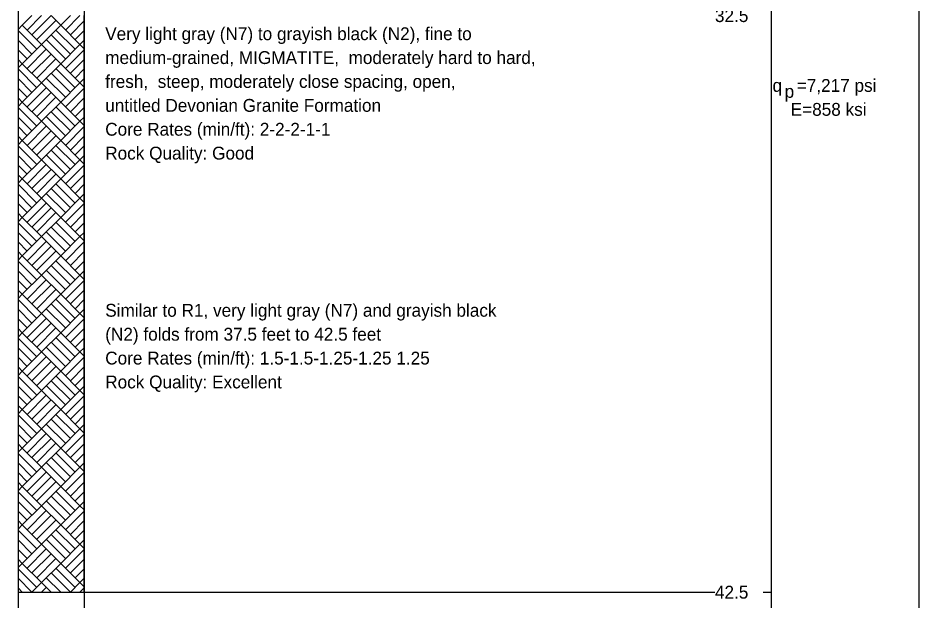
# Model space of a CAD drawing. Extents: x 9419 to 9552, y 6780 to 6865.
# Drawn here: x 9514.02 to 9529.65, y 6804.32 to 6814.43 of the extents above; entities that cross this region are included whole.
import ezdxf

# ---------------------------------------------------------------- set-up
doc = ezdxf.new("R2010")
doc.units = 0
doc.layers.add('7', color=7, linetype='Continuous')
doc.layers.add('8', color=7, linetype='Continuous')

msp = doc.modelspace()

# ---------------------------------------------------------------- linework, layer by layer
at = {"layer": '7'}
for p, q in [((9514.023, 6814.468), (9514.023, 6804.468)), ((9515.171, 6804.468), (9515.171, 6814.468)), ((9514.023, 6804.468), (9515.171, 6804.468))]:
    msp.add_line(p, q, dxfattribs=at)
for points in [[(9514.023, 6821.996), (9514.023, 6796.941)], [(9515.171, 6821.996), (9515.171, 6796.941)], [(9527.089, 6821.996), (9527.089, 6796.941)], [(9529.654, 6821.996), (9529.654, 6791.95)], [(9515.171, 6804.468), (9526.114, 6804.468)], [(9526.953, 6804.468), (9527.089, 6804.468)]]:
    msp.add_lwpolyline(points, dxfattribs=at)
at = {"layer": '8'}
for p, q in [((9514.264, 6814.468), (9514.097, 6814.302)), ((9514.431, 6814.468), (9514.181, 6814.218)), ((9514.597, 6814.468), (9514.264, 6814.135)), ((9514.597, 6814.468), (9514.764, 6814.302)), ((9514.931, 6814.468), (9514.764, 6814.302)), ((9515.097, 6814.468), (9514.847, 6814.218)), ((9514.097, 6814.302), (9514.023, 6814.228)), ((9514.097, 6814.302), (9514.431, 6813.968)), ((9514.681, 6814.385), (9514.347, 6814.052)), ((9514.764, 6814.302), (9514.431, 6813.968)), ((9514.764, 6814.302), (9514.431, 6813.968)), ((9514.764, 6814.302), (9515.097, 6813.968)), ((9515.171, 6814.376), (9514.931, 6814.135)), ((9514.023, 6814.209), (9514.347, 6813.885)), ((9514.597, 6814.135), (9514.931, 6813.802)), ((9514.681, 6814.218), (9515.014, 6813.885)), ((9515.171, 6814.209), (9515.014, 6814.052)), ((9514.023, 6814.043), (9514.264, 6813.802)), ((9514.431, 6813.968), (9514.097, 6813.635)), ((9514.431, 6813.968), (9514.097, 6813.635)), ((9514.764, 6813.635), (9514.431, 6813.968)), ((9514.431, 6813.968), (9514.764, 6813.635)), ((9514.514, 6814.052), (9514.847, 6813.718)), ((9515.097, 6813.968), (9514.764, 6813.635)), ((9515.097, 6813.968), (9514.764, 6813.635)), ((9515.171, 6814.043), (9515.097, 6813.968)), ((9515.171, 6814.043), (9515.097, 6813.968)), ((9515.171, 6813.894), (9515.097, 6813.968)), ((9515.097, 6813.968), (9515.171, 6813.894)), ((9514.023, 6813.876), (9514.181, 6813.718)), ((9514.514, 6813.885), (9514.181, 6813.552)), ((9514.597, 6813.802), (9514.264, 6813.468)), ((9515.171, 6813.876), (9514.847, 6813.552)), ((9514.097, 6813.635), (9514.023, 6813.709)), ((9514.097, 6813.635), (9514.023, 6813.561)), ((9514.097, 6813.635), (9514.431, 6813.302)), ((9514.681, 6813.718), (9514.347, 6813.385)), ((9514.764, 6813.635), (9514.431, 6813.302)), ((9514.764, 6813.635), (9514.431, 6813.302)), ((9514.764, 6813.635), (9515.097, 6813.302)), ((9515.171, 6813.709), (9514.931, 6813.468)), ((9514.023, 6813.543), (9514.347, 6813.218)), ((9514.597, 6813.468), (9514.931, 6813.135)), ((9514.681, 6813.552), (9515.014, 6813.218)), ((9515.171, 6813.543), (9515.014, 6813.385)), ((9514.023, 6813.376), (9514.264, 6813.135)), ((9514.431, 6813.302), (9514.097, 6812.968)), ((9514.431, 6813.302), (9514.097, 6812.968)), ((9514.764, 6812.968), (9514.431, 6813.302)), ((9514.431, 6813.302), (9514.764, 6812.968)), ((9514.514, 6813.385), (9514.847, 6813.052)), ((9515.097, 6813.302), (9514.764, 6812.968)), ((9515.097, 6813.302), (9514.764, 6812.968)), ((9515.171, 6813.376), (9515.097, 6813.302)), ((9515.171, 6813.376), (9515.097, 6813.302)), ((9515.171, 6813.228), (9515.097, 6813.302)), ((9515.097, 6813.302), (9515.171, 6813.228)), ((9514.023, 6813.209), (9514.181, 6813.052)), ((9514.514, 6813.218), (9514.181, 6812.885)), ((9515.171, 6813.209), (9514.847, 6812.885)), ((9514.097, 6812.968), (9514.023, 6813.043)), ((9514.597, 6813.135), (9514.264, 6812.802)), ((9514.681, 6813.052), (9514.347, 6812.718)), ((9515.171, 6813.043), (9514.931, 6812.802)), ((9514.097, 6812.968), (9514.023, 6812.894)), ((9514.023, 6812.876), (9514.347, 6812.552)), ((9514.097, 6812.968), (9514.431, 6812.635)), ((9514.764, 6812.968), (9514.431, 6812.635)), ((9514.764, 6812.968), (9514.431, 6812.635)), ((9514.681, 6812.885), (9515.014, 6812.552)), ((9514.764, 6812.968), (9515.097, 6812.635)), ((9515.171, 6812.876), (9515.014, 6812.718)), ((9514.023, 6812.709), (9514.264, 6812.468)), ((9514.514, 6812.718), (9514.847, 6812.385)), ((9514.597, 6812.802), (9514.931, 6812.468)), ((9515.171, 6812.709), (9515.097, 6812.635)), ((9515.171, 6812.709), (9515.097, 6812.635)), ((9514.023, 6812.543), (9514.181, 6812.385)), ((9514.431, 6812.635), (9514.097, 6812.302)), ((9514.431, 6812.635), (9514.097, 6812.302)), ((9514.514, 6812.552), (9514.181, 6812.218)), ((9514.764, 6812.302), (9514.431, 6812.635)), ((9514.431, 6812.635), (9514.764, 6812.302)), ((9515.097, 6812.635), (9514.764, 6812.302)), ((9515.097, 6812.635), (9514.764, 6812.302)), ((9515.171, 6812.543), (9514.847, 6812.218)), ((9515.171, 6812.561), (9515.097, 6812.635)), ((9515.097, 6812.635), (9515.171, 6812.561)), ((9514.097, 6812.302), (9514.023, 6812.376)), ((9514.597, 6812.468), (9514.264, 6812.135)), ((9514.681, 6812.385), (9514.347, 6812.052)), ((9515.171, 6812.376), (9514.931, 6812.135)), ((9514.097, 6812.302), (9514.023, 6812.228)), ((9514.023, 6812.209), (9514.347, 6811.885)), ((9514.097, 6812.302), (9514.431, 6811.968)), ((9514.764, 6812.302), (9514.431, 6811.968)), ((9514.764, 6812.302), (9514.431, 6811.968)), ((9514.681, 6812.218), (9515.014, 6811.885)), ((9514.764, 6812.302), (9515.097, 6811.968)), ((9515.171, 6812.209), (9515.014, 6812.052)), ((9514.514, 6812.052), (9514.847, 6811.718)), ((9514.597, 6812.135), (9514.931, 6811.802)), ((9514.023, 6812.043), (9514.264, 6811.802)), ((9514.431, 6811.968), (9514.097, 6811.635)), ((9514.431, 6811.968), (9514.097, 6811.635)), ((9514.764, 6811.635), (9514.431, 6811.968)), ((9514.431, 6811.968), (9514.764, 6811.635)), ((9515.097, 6811.968), (9514.764, 6811.635)), ((9515.097, 6811.968), (9514.764, 6811.635)), ((9515.171, 6812.043), (9515.097, 6811.968)), ((9515.171, 6812.043), (9515.097, 6811.968)), ((9515.171, 6811.894), (9515.097, 6811.968)), ((9515.097, 6811.968), (9515.171, 6811.894)), ((9514.023, 6811.876), (9514.181, 6811.718)), ((9514.514, 6811.885), (9514.181, 6811.552)), ((9514.597, 6811.802), (9514.264, 6811.468)), ((9515.171, 6811.876), (9514.847, 6811.552)), ((9514.097, 6811.635), (9514.023, 6811.709)), ((9514.097, 6811.635), (9514.023, 6811.561)), ((9514.097, 6811.635), (9514.431, 6811.302)), ((9514.681, 6811.718), (9514.347, 6811.385)), ((9514.764, 6811.635), (9514.431, 6811.302)), ((9514.764, 6811.635), (9514.431, 6811.302)), ((9514.764, 6811.635), (9515.097, 6811.302)), ((9515.171, 6811.709), (9514.931, 6811.468)), ((9514.023, 6811.543), (9514.347, 6811.218)), ((9514.597, 6811.468), (9514.931, 6811.135)), ((9514.681, 6811.552), (9515.014, 6811.218)), ((9515.171, 6811.543), (9515.014, 6811.385)), ((9514.023, 6811.376), (9514.264, 6811.135)), ((9514.431, 6811.302), (9514.097, 6810.968)), ((9514.431, 6811.302), (9514.097, 6810.968)), ((9514.764, 6810.968), (9514.431, 6811.302)), ((9514.431, 6811.302), (9514.764, 6810.968)), ((9514.514, 6811.385), (9514.847, 6811.052)), ((9515.097, 6811.302), (9514.764, 6810.968)), ((9515.097, 6811.302), (9514.764, 6810.968)), ((9515.171, 6811.376), (9515.097, 6811.302)), ((9515.171, 6811.376), (9515.097, 6811.302)), ((9515.171, 6811.228), (9515.097, 6811.302)), ((9515.097, 6811.302), (9515.171, 6811.228)), ((9514.023, 6811.209), (9514.181, 6811.052)), ((9514.514, 6811.218), (9514.181, 6810.885)), ((9514.597, 6811.135), (9514.264, 6810.802)), ((9515.171, 6811.209), (9514.847, 6810.885)), ((9514.097, 6810.968), (9514.023, 6811.043)), ((9514.097, 6810.968), (9514.023, 6810.894)), ((9514.097, 6810.968), (9514.431, 6810.635)), ((9514.681, 6811.052), (9514.347, 6810.718)), ((9514.764, 6810.968), (9514.431, 6810.635)), ((9514.764, 6810.968), (9514.431, 6810.635)), ((9514.764, 6810.968), (9515.097, 6810.635)), ((9515.171, 6811.043), (9514.931, 6810.802)), ((9514.023, 6810.876), (9514.347, 6810.552)), ((9514.597, 6810.802), (9514.931, 6810.468)), ((9514.681, 6810.885), (9515.014, 6810.552)), ((9515.171, 6810.876), (9515.014, 6810.718)), ((9514.023, 6810.709), (9514.264, 6810.468)), ((9514.514, 6810.718), (9514.847, 6810.385)), ((9515.171, 6810.709), (9515.097, 6810.635)), ((9515.171, 6810.709), (9515.097, 6810.635)), ((9514.023, 6810.543), (9514.181, 6810.385)), ((9514.431, 6810.635), (9514.097, 6810.302)), ((9514.431, 6810.635), (9514.097, 6810.302)), ((9514.514, 6810.552), (9514.181, 6810.218)), ((9514.764, 6810.302), (9514.431, 6810.635)), ((9514.431, 6810.635), (9514.764, 6810.302)), ((9515.097, 6810.635), (9514.764, 6810.302)), ((9515.097, 6810.635), (9514.764, 6810.302)), ((9515.171, 6810.543), (9514.847, 6810.218)), ((9515.171, 6810.561), (9515.097, 6810.635)), ((9515.097, 6810.635), (9515.171, 6810.561)), ((9514.097, 6810.302), (9514.023, 6810.376)), ((9514.597, 6810.468), (9514.264, 6810.135)), ((9514.681, 6810.385), (9514.347, 6810.052)), ((9515.171, 6810.376), (9514.931, 6810.135)), ((9514.097, 6810.302), (9514.023, 6810.228)), ((9514.023, 6810.209), (9514.347, 6809.885)), ((9514.097, 6810.302), (9514.431, 6809.968)), ((9514.764, 6810.302), (9514.431, 6809.968)), ((9514.764, 6810.302), (9514.431, 6809.968)), ((9514.681, 6810.218), (9515.014, 6809.885)), ((9514.764, 6810.302), (9515.097, 6809.968)), ((9515.171, 6810.209), (9515.014, 6810.052)), ((9514.023, 6810.043), (9514.264, 6809.802)), ((9514.514, 6810.052), (9514.847, 6809.718)), ((9514.597, 6810.135), (9514.931, 6809.802)), ((9515.171, 6810.043), (9515.097, 6809.968)), ((9515.171, 6810.043), (9515.097, 6809.968)), ((9514.023, 6809.876), (9514.181, 6809.718)), ((9514.431, 6809.968), (9514.097, 6809.635)), ((9514.431, 6809.968), (9514.097, 6809.635)), ((9514.514, 6809.885), (9514.181, 6809.552)), ((9514.764, 6809.635), (9514.431, 6809.968)), ((9514.431, 6809.968), (9514.764, 6809.635)), ((9515.097, 6809.968), (9514.764, 6809.635)), ((9515.097, 6809.968), (9514.764, 6809.635)), ((9515.171, 6809.876), (9514.847, 6809.552)), ((9515.171, 6809.894), (9515.097, 6809.968)), ((9515.097, 6809.968), (9515.171, 6809.894)), ((9514.097, 6809.635), (9514.023, 6809.709)), ((9514.597, 6809.802), (9514.264, 6809.468)), ((9514.681, 6809.718), (9514.347, 6809.385)), ((9515.171, 6809.709), (9514.931, 6809.468)), ((9514.097, 6809.635), (9514.023, 6809.561)), ((9514.097, 6809.635), (9514.431, 6809.302)), ((9514.764, 6809.635), (9514.431, 6809.302)), ((9514.764, 6809.635), (9514.431, 6809.302)), ((9514.681, 6809.552), (9515.014, 6809.218)), ((9514.764, 6809.635), (9515.097, 6809.302)), ((9514.023, 6809.543), (9514.347, 6809.218)), ((9514.597, 6809.468), (9514.931, 6809.135)), ((9515.171, 6809.543), (9515.014, 6809.385)), ((9514.023, 6809.376), (9514.264, 6809.135)), ((9514.431, 6809.302), (9514.097, 6808.968)), ((9514.431, 6809.302), (9514.097, 6808.968)), ((9514.764, 6808.968), (9514.431, 6809.302)), ((9514.431, 6809.302), (9514.764, 6808.968)), ((9514.514, 6809.385), (9514.847, 6809.052)), ((9515.097, 6809.302), (9514.764, 6808.968)), ((9515.097, 6809.302), (9514.764, 6808.968)), ((9515.171, 6809.376), (9515.097, 6809.302)), ((9515.171, 6809.376), (9515.097, 6809.302)), ((9515.171, 6809.228), (9515.097, 6809.302)), ((9515.097, 6809.302), (9515.171, 6809.228)), ((9514.023, 6809.209), (9514.181, 6809.052)), ((9514.514, 6809.218), (9514.181, 6808.885)), ((9514.597, 6809.135), (9514.264, 6808.802)), ((9515.171, 6809.209), (9514.847, 6808.885)), ((9514.097, 6808.968), (9514.023, 6809.043)), ((9514.097, 6808.968), (9514.023, 6808.894)), ((9514.097, 6808.968), (9514.431, 6808.635)), ((9514.681, 6809.052), (9514.347, 6808.718)), ((9514.764, 6808.968), (9514.431, 6808.635)), ((9514.764, 6808.968), (9514.431, 6808.635)), ((9514.764, 6808.968), (9515.097, 6808.635)), ((9515.171, 6809.043), (9514.931, 6808.802)), ((9514.023, 6808.876), (9514.347, 6808.552)), ((9514.597, 6808.802), (9514.931, 6808.468)), ((9514.681, 6808.885), (9515.014, 6808.552)), ((9515.171, 6808.876), (9515.014, 6808.718)), ((9514.023, 6808.709), (9514.264, 6808.468)), ((9514.431, 6808.635), (9514.097, 6808.302)), ((9514.431, 6808.635), (9514.097, 6808.302)), ((9514.764, 6808.302), (9514.431, 6808.635)), ((9514.431, 6808.635), (9514.764, 6808.302)), ((9514.514, 6808.718), (9514.847, 6808.385)), ((9515.097, 6808.635), (9514.764, 6808.302)), ((9515.097, 6808.635), (9514.764, 6808.302)), ((9515.171, 6808.709), (9515.097, 6808.635)), ((9515.171, 6808.709), (9515.097, 6808.635)), ((9515.171, 6808.561), (9515.097, 6808.635)), ((9515.097, 6808.635), (9515.171, 6808.561)), ((9514.023, 6808.543), (9514.181, 6808.385)), ((9514.514, 6808.552), (9514.181, 6808.218)), ((9514.597, 6808.468), (9514.264, 6808.135)), ((9515.171, 6808.543), (9514.847, 6808.218)), ((9514.097, 6808.302), (9514.023, 6808.376)), ((9514.097, 6808.302), (9514.023, 6808.228)), ((9514.097, 6808.302), (9514.431, 6807.968)), ((9514.681, 6808.385), (9514.347, 6808.052)), ((9514.764, 6808.302), (9514.431, 6807.968)), ((9514.764, 6808.302), (9514.431, 6807.968)), ((9514.764, 6808.302), (9515.097, 6807.968)), ((9515.171, 6808.376), (9514.931, 6808.135)), ((9514.023, 6808.209), (9514.347, 6807.885)), ((9514.681, 6808.218), (9515.014, 6807.885)), ((9515.171, 6808.209), (9515.014, 6808.052)), ((9514.023, 6808.043), (9514.264, 6807.802)), ((9514.514, 6808.052), (9514.847, 6807.718)), ((9514.597, 6808.135), (9514.931, 6807.802)), ((9515.171, 6808.043), (9515.097, 6807.968)), ((9515.171, 6808.043), (9515.097, 6807.968)), ((9514.023, 6807.876), (9514.181, 6807.718)), ((9514.431, 6807.968), (9514.097, 6807.635)), ((9514.431, 6807.968), (9514.097, 6807.635)), ((9514.514, 6807.885), (9514.181, 6807.552)), ((9514.764, 6807.635), (9514.431, 6807.968)), ((9514.431, 6807.968), (9514.764, 6807.635)), ((9515.097, 6807.968), (9514.764, 6807.635)), ((9515.097, 6807.968), (9514.764, 6807.635)), ((9515.171, 6807.876), (9514.847, 6807.552)), ((9515.171, 6807.894), (9515.097, 6807.968)), ((9515.097, 6807.968), (9515.171, 6807.894)), ((9514.097, 6807.635), (9514.023, 6807.709)), ((9514.597, 6807.802), (9514.264, 6807.468)), ((9514.681, 6807.718), (9514.347, 6807.385)), ((9515.171, 6807.709), (9514.931, 6807.468)), ((9514.097, 6807.635), (9514.023, 6807.561)), ((9514.023, 6807.543), (9514.347, 6807.218)), ((9514.097, 6807.635), (9514.431, 6807.302)), ((9514.764, 6807.635), (9514.431, 6807.302)), ((9514.764, 6807.635), (9514.431, 6807.302)), ((9514.681, 6807.552), (9515.014, 6807.218)), ((9514.764, 6807.635), (9515.097, 6807.302)), ((9515.171, 6807.543), (9515.014, 6807.385)), ((9514.023, 6807.376), (9514.264, 6807.135)), ((9514.514, 6807.385), (9514.847, 6807.052)), ((9514.597, 6807.468), (9514.931, 6807.135)), ((9515.171, 6807.376), (9515.097, 6807.302)), ((9515.171, 6807.376), (9515.097, 6807.302)), ((9514.023, 6807.209), (9514.181, 6807.052)), ((9514.431, 6807.302), (9514.097, 6806.968)), ((9514.431, 6807.302), (9514.097, 6806.968)), ((9514.514, 6807.218), (9514.181, 6806.885)), ((9514.764, 6806.968), (9514.431, 6807.302)), ((9514.431, 6807.302), (9514.764, 6806.968)), ((9515.097, 6807.302), (9514.764, 6806.968)), ((9515.097, 6807.302), (9514.764, 6806.968)), ((9515.171, 6807.209), (9514.847, 6806.885)), ((9515.171, 6807.228), (9515.097, 6807.302)), ((9515.097, 6807.302), (9515.171, 6807.228)), ((9514.597, 6807.135), (9514.264, 6806.802)), ((9514.681, 6807.052), (9514.347, 6806.718)), ((9514.097, 6806.968), (9514.023, 6807.043)), ((9514.097, 6806.968), (9514.023, 6806.894)), ((9514.097, 6806.968), (9514.431, 6806.635)), ((9514.764, 6806.968), (9514.431, 6806.635)), ((9514.764, 6806.968), (9514.431, 6806.635)), ((9514.764, 6806.968), (9515.097, 6806.635)), ((9515.171, 6807.043), (9514.931, 6806.802)), ((9514.023, 6806.876), (9514.347, 6806.552)), ((9514.597, 6806.802), (9514.931, 6806.468)), ((9514.681, 6806.885), (9515.014, 6806.552)), ((9515.171, 6806.876), (9515.014, 6806.718)), ((9514.023, 6806.709), (9514.264, 6806.468)), ((9514.431, 6806.635), (9514.097, 6806.302)), ((9514.431, 6806.635), (9514.097, 6806.302)), ((9514.764, 6806.302), (9514.431, 6806.635)), ((9514.431, 6806.635), (9514.764, 6806.302)), ((9514.514, 6806.718), (9514.847, 6806.385)), ((9515.097, 6806.635), (9514.764, 6806.302)), ((9515.097, 6806.635), (9514.764, 6806.302)), ((9515.171, 6806.709), (9515.097, 6806.635)), ((9515.171, 6806.709), (9515.097, 6806.635)), ((9515.171, 6806.561), (9515.097, 6806.635)), ((9515.097, 6806.635), (9515.171, 6806.561)), ((9514.023, 6806.543), (9514.181, 6806.385)), ((9514.514, 6806.552), (9514.181, 6806.218)), ((9514.597, 6806.468), (9514.264, 6806.135)), ((9515.171, 6806.543), (9514.847, 6806.218)), ((9514.097, 6806.302), (9514.023, 6806.376)), ((9514.097, 6806.302), (9514.023, 6806.228)), ((9514.097, 6806.302), (9514.431, 6805.968)), ((9514.681, 6806.385), (9514.347, 6806.052)), ((9514.764, 6806.302), (9514.431, 6805.968)), ((9514.764, 6806.302), (9514.431, 6805.968)), ((9514.764, 6806.302), (9515.097, 6805.968)), ((9515.171, 6806.376), (9514.931, 6806.135)), ((9514.023, 6806.209), (9514.347, 6805.885)), ((9514.597, 6806.135), (9514.931, 6805.802)), ((9514.681, 6806.218), (9515.014, 6805.885)), ((9515.171, 6806.209), (9515.014, 6806.052)), ((9514.023, 6806.043), (9514.264, 6805.802)), ((9514.431, 6805.968), (9514.097, 6805.635)), ((9514.431, 6805.968), (9514.097, 6805.635)), ((9514.764, 6805.635), (9514.431, 6805.968)), ((9514.431, 6805.968), (9514.764, 6805.635)), ((9514.514, 6806.052), (9514.847, 6805.718)), ((9515.097, 6805.968), (9514.764, 6805.635)), ((9515.097, 6805.968), (9514.764, 6805.635)), ((9515.171, 6806.043), (9515.097, 6805.968)), ((9515.171, 6806.043), (9515.097, 6805.968)), ((9515.171, 6805.894), (9515.097, 6805.968)), ((9515.097, 6805.968), (9515.171, 6805.894)), ((9514.023, 6805.876), (9514.181, 6805.718)), ((9514.514, 6805.885), (9514.181, 6805.552)), ((9514.597, 6805.802), (9514.264, 6805.468)), ((9515.171, 6805.876), (9514.847, 6805.552)), ((9514.097, 6805.635), (9514.023, 6805.709)), ((9514.681, 6805.718), (9514.347, 6805.385)), ((9515.171, 6805.709), (9514.931, 6805.468)), ((9514.097, 6805.635), (9514.023, 6805.561)), ((9514.023, 6805.543), (9514.347, 6805.218)), ((9514.097, 6805.635), (9514.431, 6805.302)), ((9514.764, 6805.635), (9514.431, 6805.302)), ((9514.764, 6805.635), (9514.431, 6805.302)), ((9514.681, 6805.552), (9515.014, 6805.218)), ((9514.764, 6805.635), (9515.097, 6805.302)), ((9515.171, 6805.543), (9515.014, 6805.385)), ((9514.023, 6805.376), (9514.264, 6805.135)), ((9514.514, 6805.385), (9514.847, 6805.052)), ((9514.597, 6805.468), (9514.931, 6805.135)), ((9515.171, 6805.376), (9515.097, 6805.302)), ((9515.171, 6805.376), (9515.097, 6805.302)), ((9514.023, 6805.209), (9514.181, 6805.052)), ((9514.431, 6805.302), (9514.097, 6804.968)), ((9514.431, 6805.302), (9514.097, 6804.968)), ((9514.514, 6805.218), (9514.181, 6804.885)), ((9514.764, 6804.968), (9514.431, 6805.302)), ((9514.431, 6805.302), (9514.764, 6804.968)), ((9515.097, 6805.302), (9514.764, 6804.968)), ((9515.097, 6805.302), (9514.764, 6804.968)), ((9515.171, 6805.209), (9514.847, 6804.885)), ((9515.171, 6805.228), (9515.097, 6805.302)), ((9515.097, 6805.302), (9515.171, 6805.228)), ((9514.097, 6804.968), (9514.023, 6805.043)), ((9514.597, 6805.135), (9514.264, 6804.802)), ((9514.681, 6805.052), (9514.347, 6804.718)), ((9515.171, 6805.043), (9514.931, 6804.802)), ((9514.097, 6804.968), (9514.023, 6804.894)), ((9514.023, 6804.876), (9514.347, 6804.552)), ((9514.097, 6804.968), (9514.431, 6804.635)), ((9514.764, 6804.968), (9514.431, 6804.635)), ((9514.764, 6804.968), (9514.431, 6804.635)), ((9514.681, 6804.885), (9515.014, 6804.552)), ((9514.764, 6804.968), (9515.097, 6804.635)), ((9515.171, 6804.876), (9515.014, 6804.718)), ((9514.023, 6804.709), (9514.264, 6804.468)), ((9514.514, 6804.718), (9514.764, 6804.468)), ((9514.597, 6804.802), (9514.931, 6804.468)), ((9515.171, 6804.709), (9515.097, 6804.635)), ((9515.171, 6804.709), (9515.097, 6804.635)), ((9514.431, 6804.635), (9514.264, 6804.468)), ((9514.431, 6804.635), (9514.264, 6804.468)), ((9514.597, 6804.468), (9514.431, 6804.635)), ((9514.431, 6804.635), (9514.597, 6804.468)), ((9514.514, 6804.552), (9514.431, 6804.468)), ((9515.097, 6804.635), (9514.931, 6804.468)), ((9515.097, 6804.635), (9514.931, 6804.468)), ((9515.171, 6804.561), (9515.097, 6804.635)), ((9515.097, 6804.635), (9515.171, 6804.561)), ((9514.023, 6804.543), (9514.097, 6804.468)), ((9514.597, 6804.468), (9514.597, 6804.468)), ((9515.171, 6804.543), (9515.097, 6804.468))]:
    msp.add_line(p, q, dxfattribs=at)

# ---------------------------------------------------------------- texts
at = {"layer": '7'}
for s, height, p in [('32.5', 0.2228, (9526.114, 6814.357)), ('Very light gray (N7) to grayish black (N2), fine to', 0.2228, (9515.536, 6814.043)), ('medium-grained, MIGMATITE,  moderately hard to hard,', 0.2228, (9515.536, 6813.629)), ('fresh,  steep, moderately close spacing, open,', 0.2228, (9515.536, 6813.215)), ('q', 0.223, (9527.113, 6813.146)), ('=7,217 psi', 0.2228, (9527.533, 6813.146)), ('p', 0.223, (9527.323, 6813.042)), ('untitled Devonian Granite Formation', 0.2228, (9515.536, 6812.8)), ('E=858 ksi', 0.2228, (9527.428, 6812.731)), ('Core Rates (min/ft): 2-2-2-1-1', 0.2228, (9515.536, 6812.386)), ('Rock Quality: Good', 0.2228, (9515.536, 6811.972)), ('Similar to R1, very light gray (N7) and grayish black', 0.2228, (9515.536, 6809.246)), ('(N2) folds from 37.5 feet to 42.5 feet', 0.2228, (9515.536, 6808.831)), ('Core Rates (min/ft): 1.5-1.5-1.25-1.25 1.25', 0.2228, (9515.536, 6808.417)), ('Rock Quality: Excellent', 0.2228, (9515.536, 6808.003)), ('42.5', 0.2228, (9526.114, 6804.357))]:
    msp.add_text(s, height=height, dxfattribs=at).set_placement(p)

doc.saveas('drawing.dxf')
